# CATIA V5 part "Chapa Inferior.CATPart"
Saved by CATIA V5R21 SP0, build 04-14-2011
Part number: Chapa Inferior
Definition: Chapa Inferior
Nomenclature: Chapa Inferior
Source: Unknown
Bounding box of the stored display mesh (mm): x -6 to 6, y 0 to 0.8, z -5 to 5
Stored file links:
  C:\Users\beatr\OneDrive\Documents\UNB\2026_1\Pi1\Componentes eletronicos\Chapa Inferior.CATPart
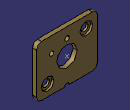
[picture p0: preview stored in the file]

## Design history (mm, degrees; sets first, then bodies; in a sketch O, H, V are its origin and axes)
Set1
  Point1 "CARTESIAN_POINT #66507": stored without definition
Body1 "Sólido2" (main body)
  Solid1: solid without history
